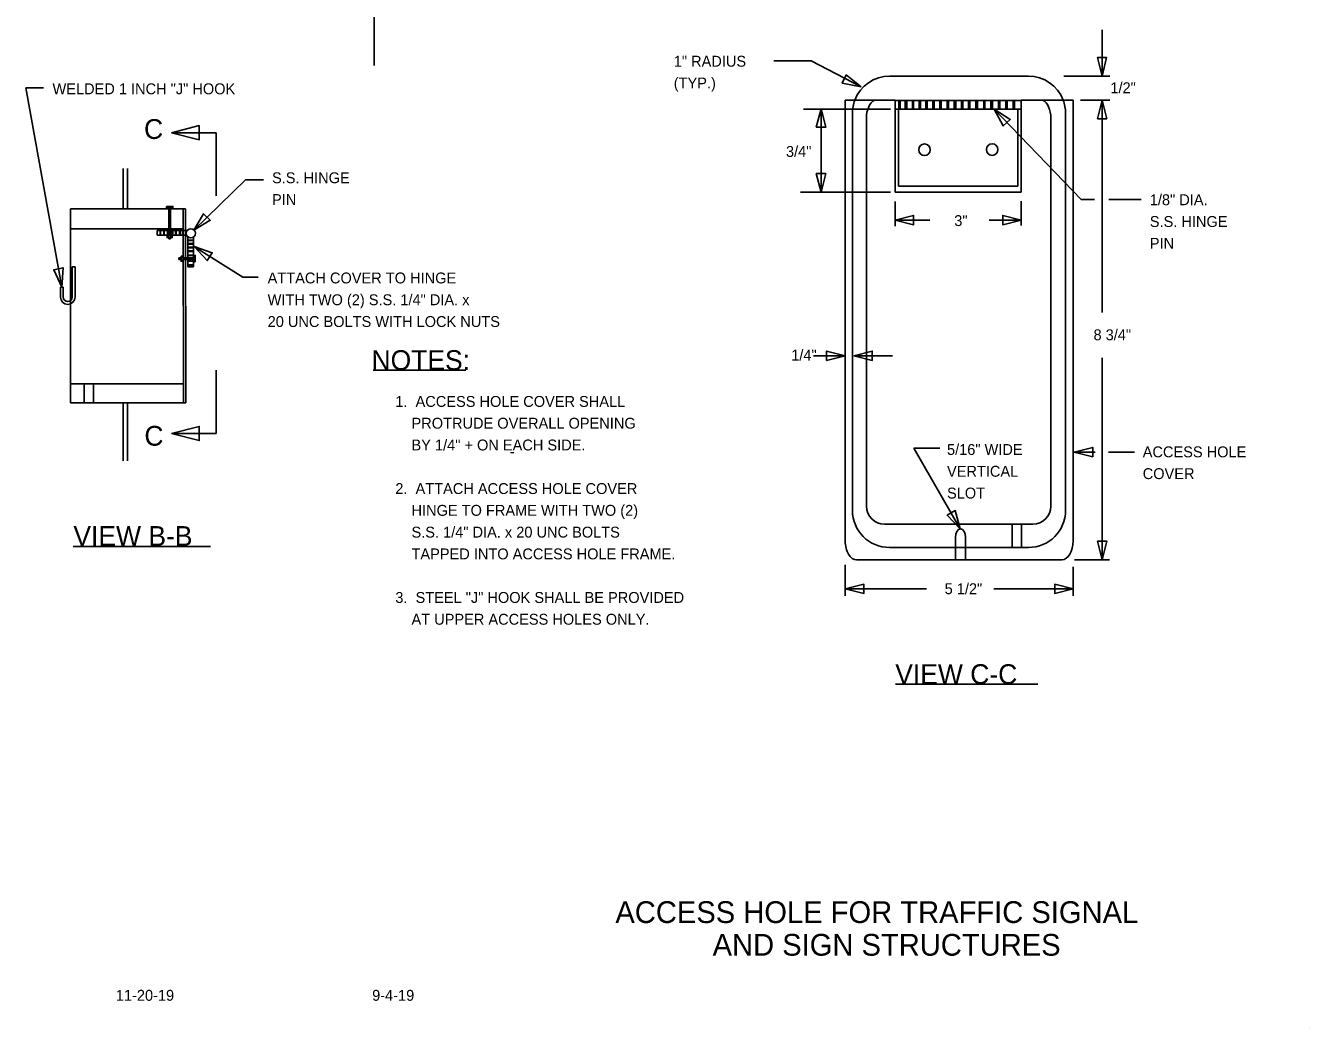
# Model space of a CAD drawing. Extents: x 12.6 to 19.6, y 6 to 19.7.
# Drawn here: x 12.55 to 19.62, y 5.99 to 11.51 of the extents above; entities that cross this region are included whole.
import ezdxf

# ---------------------------------------------------------------- set-up
doc = ezdxf.new("R2010")
doc.units = 0
for name, color, linetype in [('DETL-DIMS', 7, 'Continuous'), ('DETL-LINE', 7, 'Continuous'), ('DETL-NOTE', 7, 'Continuous'), ('DETL-TITL', 7, 'Continuous'), ('TTLB-TEXT', 7, 'Continuous')]:
    doc.layers.add(name, color=color, linetype=linetype)

msp = doc.modelspace()

# ---------------------------------------------------------------- linework, layer by layer
at = {"layer": 'DETL-DIMS'}
for p, q in [((14.4699, 15.6071), (14.4699, 11.2911)), ((18.4799, 11.2321), (18.4799, 11.4871)), ((16.6719, 11.3171), (16.8779, 11.3171)), ((17.1529, 11.1731), (16.8779, 11.3171)), ((18.2689, 11.2321), (18.5219, 11.2321)), ((12.7499, 10.0701), (12.5509, 11.1671)), ((12.5509, 11.1671), (12.6499, 11.1671)), ((16.8349, 11.0501), (17.3139, 11.0501)), ((16.9319, 10.5931), (16.9319, 11.0521)), ((17.8849, 11.0501), (18.3639, 10.5531)), ((18.3609, 11.1001), (18.5219, 11.1001)), ((18.4799, 9.9291), (18.4799, 11.1001)), ((13.3539, 10.9201), (13.6009, 10.9201)), ((13.6009, 10.9201), (13.6009, 10.5721)), ((13.4769, 10.3841), (13.7619, 10.6601)), ((13.7619, 10.6601), (13.8609, 10.6601)), ((16.8179, 10.5931), (17.3139, 10.5931)), ((17.3399, 10.4051), (17.3399, 10.5421)), ((18.0349, 10.4091), (18.0349, 10.5431)), ((18.4379, 10.5531), (18.3639, 10.5531)), ((18.6959, 10.5531), (18.5179, 10.5531)), ((17.5309, 10.4391), (17.3399, 10.4391)), ((18.0349, 10.4391), (17.8579, 10.4391)), ((13.4809, 10.2911), (13.7479, 10.1241)), ((13.7479, 10.1241), (13.8319, 10.1241)), ((17.0649, 9.6911), (16.8899, 9.6911)), ((17.1119, 9.6911), (17.3259, 9.6911)), ((18.4799, 8.5671), (18.4799, 9.6801)), ((13.6009, 9.6114), (13.6009, 9.2631)), ((13.3539, 9.2631), (13.6009, 9.2631)), ((17.6989, 8.7371), (17.4429, 9.1831)), ((17.5859, 9.1831), (17.4429, 9.1831)), ((18.4419, 9.1611), (18.3269, 9.1611)), ((18.6589, 9.1611), (18.5159, 9.1611)), ((18.3279, 8.5671), (18.5199, 8.5671)), ((17.0649, 8.5401), (17.0649, 8.3681)), ((18.3209, 8.5281), (18.3209, 8.3681)), ((17.0649, 8.4071), (17.5129, 8.4071)), ((17.8839, 8.4071), (18.3209, 8.4071))]:
    msp.add_line(p, q, dxfattribs=at)
for points in [[(18.4799, 11.2321), (18.4539, 11.3341), (18.5049, 11.3341)], [(17.1529, 11.1731), (17.0489, 11.1931), (17.0709, 11.2391)], [(16.9319, 11.0521), (16.9059, 10.9501), (16.9579, 10.9501)], [(17.8849, 11.0501), (17.9359, 10.9581), (17.9739, 10.9931)], [(18.4799, 11.1001), (18.4549, 10.9971), (18.5059, 10.9971)], [(13.3539, 10.9201), (13.5069, 10.8811), (13.5069, 10.9591)], [(16.9319, 10.5931), (16.9059, 10.6951), (16.9579, 10.6951)], [(13.4769, 10.3841), (13.5309, 10.4741), (13.5679, 10.4381)], [(17.3399, 10.4391), (17.4419, 10.4131), (17.4419, 10.4651)], [(18.0349, 10.4391), (17.9329, 10.4131), (17.9329, 10.4651)], [(13.4789, 10.2931), (13.5509, 10.2161), (13.5789, 10.2591)], [(12.7499, 10.0701), (12.7059, 10.1651), (12.7569, 10.1761)], [(17.0649, 9.6911), (16.9629, 9.6661), (16.9629, 9.7171)], [(17.1119, 9.6911), (17.2139, 9.6661), (17.2139, 9.7171)], [(13.3539, 9.2631), (13.5069, 9.2241), (13.5069, 9.3021)], [(18.3269, 9.1611), (18.4289, 9.1351), (18.4289, 9.1861)], [(17.6989, 8.7371), (17.6709, 8.8381), (17.6259, 8.8131)], [(18.4799, 8.5671), (18.5059, 8.6701), (18.4549, 8.6701)], [(17.0649, 8.4071), (17.1679, 8.3821), (17.1679, 8.4331)], [(18.3209, 8.4071), (18.2189, 8.3821), (18.2189, 8.4331)]]:
    msp.add_lwpolyline(points, close=True, dxfattribs=at)
at = {"layer": 'DETL-LINE'}
for p, q in [((17.3099, 11.2321), (18.0739, 11.2321)), ((17.3399, 11.1001), (17.0649, 11.1001)), ((17.0649, 11.1001), (17.0649, 8.6711)), ((17.3399, 11.1001), (17.3399, 10.5931)), ((17.3399, 11.0981), (18.0349, 11.0981)), ((17.3399, 11.0501), (18.0349, 11.0501)), ((17.3589, 10.6251), (17.3589, 11.0501)), ((17.3599, 11.0941), (17.3599, 11.0461)), ((17.3679, 11.0941), (17.3679, 11.0461)), ((17.3959, 11.0941), (17.3959, 11.0461)), ((17.4039, 11.0941), (17.4039, 11.0461)), ((17.4349, 11.0941), (17.4349, 11.0461)), ((17.4419, 11.0941), (17.4419, 11.0461)), ((17.4729, 11.0941), (17.4729, 11.0461)), ((17.4799, 11.0941), (17.4799, 11.0461)), ((17.5089, 11.0941), (17.5089, 11.0461)), ((17.5159, 11.0941), (17.5159, 11.0461)), ((17.5469, 11.0941), (17.5469, 11.0461)), ((17.5549, 11.0941), (17.5549, 11.0461)), ((17.5859, 11.0941), (17.5859, 11.0461)), ((17.5929, 11.0941), (17.5929, 11.0461)), ((17.6259, 11.0941), (17.6259, 11.0461)), ((17.6339, 11.0941), (17.6339, 11.0461)), ((17.6649, 11.0941), (17.6649, 11.0461)), ((17.6739, 11.0941), (17.6739, 11.0461)), ((17.7059, 11.0941), (17.7059, 11.0461)), ((17.7129, 11.0941), (17.7129, 11.0461)), ((17.7439, 11.0941), (17.7439, 11.0461)), ((17.7509, 11.0941), (17.7509, 11.0461)), ((17.7849, 11.0941), (17.7849, 11.0461)), ((17.7939, 11.0941), (17.7939, 11.0461)), ((17.8279, 11.0941), (17.8279, 11.0461)), ((17.8349, 11.0941), (17.8349, 11.0461)), ((17.8679, 11.0941), (17.8679, 11.0461)), ((17.8759, 11.0941), (17.8759, 11.0461)), ((17.9089, 11.0941), (17.9089, 11.0461)), ((17.9159, 11.0941), (17.9159, 11.0461)), ((17.9499, 11.0941), (17.9499, 11.0461)), ((17.9569, 11.0941), (17.9569, 11.0461)), ((17.9909, 11.0941), (17.9909, 11.0461)), ((17.9979, 11.0941), (17.9979, 11.0461)), ((18.0159, 10.6251), (18.0159, 11.0501)), ((18.0349, 10.5931), (18.0349, 11.1001)), ((18.3209, 11.1001), (18.0349, 11.1001)), ((18.3209, 8.6711), (18.3209, 11.1001)), ((17.1049, 11.0271), (17.1049, 8.8401)), ((17.1819, 11.0051), (17.1819, 8.8631)), ((18.1979, 11.0001), (18.1979, 8.8631)), ((18.2789, 11.0271), (18.2789, 8.8401)), ((13.0879, 10.7231), (13.0879, 10.5011)), ((13.1119, 10.7231), (13.1119, 10.5011)), ((17.3589, 10.6251), (18.0159, 10.6251)), ((17.3399, 10.5931), (18.0349, 10.5931)), ((12.7979, 10.5011), (12.7979, 9.4321)), ((13.4319, 10.5011), (12.7979, 10.5011)), ((13.3389, 10.5071), (13.3389, 10.3541)), ((13.3489, 10.5071), (13.3489, 10.3541)), ((13.4189, 10.5011), (13.4209, 9.4321)), ((13.4319, 10.5011), (13.4329, 9.4321)), ((13.4189, 10.3901), (12.7979, 10.3901)), ((13.2759, 10.3811), (13.2759, 10.3561)), ((13.2759, 10.3811), (13.4399, 10.3811)), ((13.2759, 10.3561), (13.4379, 10.3561)), ((13.2919, 10.3811), (13.2919, 10.3571)), ((13.2939, 10.3811), (13.2939, 10.3571)), ((13.3119, 10.3811), (13.3119, 10.3571)), ((13.3139, 10.3811), (13.3139, 10.3571)), ((13.3329, 10.3811), (13.3329, 10.3571)), ((13.3339, 10.3811), (13.3339, 10.3571)), ((13.3359, 10.3541), (13.3359, 10.3421)), ((13.3389, 10.3421), (13.3389, 10.3351)), ((13.3489, 10.3351), (13.3389, 10.3351)), ((13.3489, 10.3421), (13.3489, 10.3351)), ((13.3509, 10.3541), (13.3509, 10.3421)), ((13.3579, 10.3811), (13.3579, 10.3571)), ((13.3609, 10.3811), (13.3609, 10.3571)), ((13.3769, 10.3811), (13.3769, 10.3571)), ((13.3799, 10.3811), (13.3799, 10.3571)), ((13.3989, 10.3811), (13.3989, 10.3571)), ((13.4019, 10.3811), (13.4019, 10.3571)), ((13.4149, 10.3811), (13.4149, 10.3571)), ((13.4169, 10.3811), (13.4169, 10.3571)), ((13.4449, 10.1811), (13.4449, 10.3461)), ((13.4449, 10.3291), (13.4749, 10.3291)), ((13.4449, 10.3261), (13.4749, 10.3261)), ((13.4759, 10.1811), (13.4759, 10.3461)), ((13.4449, 10.3091), (13.4749, 10.3091)), ((13.4449, 10.3061), (13.4749, 10.3061)), ((13.4449, 10.2891), (13.4749, 10.2891)), ((13.4449, 10.2861), (13.4749, 10.2861)), ((13.4449, 10.2691), (13.4749, 10.2691)), ((13.4449, 10.2661), (13.4749, 10.2661)), ((13.4069, 10.2301), (13.3949, 10.2301)), ((13.3949, 10.2301), (13.3949, 10.2211)), ((13.4069, 10.2211), (13.3949, 10.2211)), ((13.4189, 10.2331), (13.4069, 10.2331)), ((13.4189, 10.2181), (13.4069, 10.2181)), ((13.4769, 10.2301), (13.4189, 10.2301)), ((13.4769, 10.2211), (13.4189, 10.2211)), ((13.4449, 10.2461), (13.4749, 10.2461)), ((13.4449, 10.2431), (13.4749, 10.2431)), ((13.4449, 10.2161), (13.4749, 10.2161)), ((13.4449, 10.2131), (13.4749, 10.2131)), ((13.4449, 10.1931), (13.4749, 10.1931)), ((13.4449, 10.1901), (13.4749, 10.1901)), ((12.8079, 10.1811), (12.8229, 10.1811)), ((12.8079, 10.1811), (12.8079, 10.0141)), ((12.8229, 10.1811), (12.8229, 10.0141)), ((13.4449, 10.1811), (13.4759, 10.1811)), ((12.7579, 10.0701), (12.7429, 10.0701)), ((12.7429, 10.0701), (12.7429, 10.0141)), ((12.7579, 10.0701), (12.7579, 10.0141)), ((12.7979, 9.5361), (13.4209, 9.5361)), ((12.8729, 9.5361), (12.8729, 9.4321)), ((12.9239, 9.5361), (12.9239, 9.4321)), ((12.7979, 9.4321), (13.1879, 9.4321)), ((13.0879, 9.4321), (13.0879, 9.1121)), ((13.1119, 9.4321), (13.1119, 9.1121)), ((13.4329, 9.4321), (13.1729, 9.4321)), ((17.2819, 8.7631), (18.0979, 8.7631)), ((17.6999, 8.7371), (17.6999, 8.7371)), ((17.9839, 8.7631), (17.9839, 8.6351)), ((18.0359, 8.7631), (18.0359, 8.6351)), ((17.3099, 8.6351), (18.0739, 8.6351)), ((17.6719, 8.5671), (17.6719, 8.6911)), ((17.7279, 8.5671), (17.7279, 8.6911)), ((17.1279, 8.5671), (18.2589, 8.5671))]:
    msp.add_line(p, q, dxfattribs=at)
for points in [[(13.3259, 10.5141), (13.3619, 10.5141), (13.3619, 10.5071), (13.3259, 10.5071)], [(13.3299, 10.3541), (13.3579, 10.3541), (13.3579, 10.3421), (13.3299, 10.3421)], [(13.4189, 10.2121), (13.4189, 10.2401), (13.4069, 10.2401), (13.4069, 10.2121)], [(13.4849, 10.2081), (13.4849, 10.2441), (13.4769, 10.2441), (13.4769, 10.2081)]]:
    msp.add_lwpolyline(points, close=True, dxfattribs=at)
for centre, radius in [((17.5017, 10.8263), 0.032), ((17.8746, 10.8274), 0.032), ((13.4606, 10.3662), 0.0251)]:
    msp.add_circle(centre, radius, dxfattribs=at)
for centre, radius, start, end in [((17.3095, 11.0275), 0.2046, 90, 159.23728), ((18.0743, 11.0275), 0.2046, 20.76272, 90), ((17.3095, 11.0275), 0.2046, 159.23728, 180), ((18.0743, 11.0275), 0.2046, 0, 20.76272), ((12.7829, 10.0146), 0.04, 180, 0), ((12.7829, 10.0146), 0.025, 180, 0), ((17.3095, 8.8397), 0.2046, 180, 270), ((17.2819, 8.8631), 0.1, 180, 270), ((18.0743, 8.8397), 0.2046, 270, 360), ((18.0979, 8.8631), 0.1, 270, 360)]:
    msp.add_arc(centre, radius, start, end, dxfattribs=at)
for centre, major_axis, start_param, end_param in [((17.2443, 11.0001), (0, 0.1042), 0.281105, 1.570796), ((18.1354, 11.0001), (0, 0.1042), 4.712389, 6.00208), ((17.6994, 8.6913), (0, 0.0458), 0, 1.570796), ((17.7, 8.6913), (0, 0.0458), 4.712389, 6.283185), ((17.1279, 8.6716), (0, 0.1042), 1.570796, 3.141593), ((18.2584, 8.6716), (0, -0.1042), 0, 1.570796)]:
    msp.add_ellipse(centre, major_axis=major_axis, ratio=0.6, start_param=start_param, end_param=end_param, dxfattribs=at)
at = {"layer": 'DETL-NOTE'}
msp.add_line((14.4645, 9.6126), (14.9749, 9.6126), dxfattribs=at)
at = {"layer": 'DETL-TITL'}
for p, q in [((12.8122, 8.6402), (13.5687, 8.6402)), ((17.3412, 7.8816), (18.1261, 7.8816))]:
    msp.add_line(p, q, dxfattribs=at)
at = {"layer": 'TTLB-TEXT'}
msp.add_line((19.6215, 5.9917), (19.6215, 5.9917), dxfattribs=at)

# ---------------------------------------------------------------- texts
at = {"layer": 'DETL-NOTE'}
for s, height, p in [('1" RADIUS', 0.06, (16.1208, 11.284)), ('WELDED 1 INCH "J" HOOK', 0.06, (12.6988, 11.132)), ('(TYP.)', 0.06, (16.1208, 11.164)), ('1/2"', 0.06, (18.5258, 11.138)), ('C', 0.109, (13.2028, 10.886)), ('3/4"', 0.06, (16.7388, 10.787)), ('S.S. HINGE', 0.06, (13.9078, 10.642)), ('PIN', 0.06, (13.9078, 10.522)), ('1/8" DIA.', 0.06, (18.7428, 10.521)), ('3"', 0.06, (17.6658, 10.406)), ('S.S. HINGE', 0.06, (18.7428, 10.401)), ('PIN', 0.06, (18.7428, 10.281)), ('ATTACH COVER TO HINGE', 0.06, (13.8838, 10.09)), ('WITH TWO (2) S.S. 1/4" DIA. x', 0.06, (13.8838, 9.97)), ('20 UNC BOLTS WITH LOCK NUTS', 0.06, (13.8838, 9.85)), ('8 3/4"', 0.06, (18.4328, 9.777)), ('NOTES:', 0.109, (14.4558, 9.613)), ('1/4"', 0.06, (16.7678, 9.665)), ('1.  ACCESS HOLE COVER SHALL', 0.06, (14.587, 9.4098)), ('    PROTRUDE OVERALL OPENING', 0.06, (14.587, 9.2898)), ('C', 0.109, (13.2048, 9.196)), ('    BY 1/4" + ON EACH SIDE.', 0.06, (14.587, 9.1698)), ('5/16" WIDE', 0.06, (17.6258, 9.145)), ('ACCESS HOLE', 0.06, (18.7038, 9.132)), ('-', 0.06, (15.2167, 9.135)), ('VERTICAL', 0.06, (17.6258, 9.025)), ('COVER', 0.06, (18.7038, 9.012)), ('2.  ATTACH ACCESS HOLE COVER', 0.06, (14.587, 8.9298)), ('SLOT', 0.06, (17.6258, 8.905)), ('    HINGE TO FRAME WITH TWO (2)', 0.06, (14.587, 8.8098)), ('    S.S. 1/4" DIA. x 20 UNC BOLTS', 0.06, (14.587, 8.6898)), ('    TAPPED INTO ACCESS HOLE FRAME.', 0.06, (14.587, 8.5698)), ('5 1/2"', 0.06, (17.6128, 8.378)), ('3.  STEEL "J" HOOK SHALL BE PROVIDED', 0.06, (14.587, 8.3298)), ('    AT UPPER ACCESS HOLES ONLY.', 0.06, (14.587, 8.2098))]:
    msp.add_text(s, height=height, dxfattribs=at).set_placement(p)
at = {"layer": 'DETL-TITL'}
for s, p in [('VIEW B-B', (12.8138, 8.644)), ('VIEW C-C', (17.3408, 7.883))]:
    msp.add_text(s, height=0.109, dxfattribs=at).set_placement(p)
at = {"layer": 'TTLB-TEXT'}
for s, height, p in [('ACCESS HOLE FOR TRAFFIC SIGNAL', 0.12, (15.7991, 6.5663)), ('AND SIGN STRUCTURES', 0.12, (16.3347, 6.3863)), ('11-20-19', 0.06, (13.0474, 6.1381)), ('9-4-19', 0.06, (14.4593, 6.1381))]:
    msp.add_text(s, height=height, dxfattribs=at).set_placement(p)

doc.saveas('drawing.dxf')
